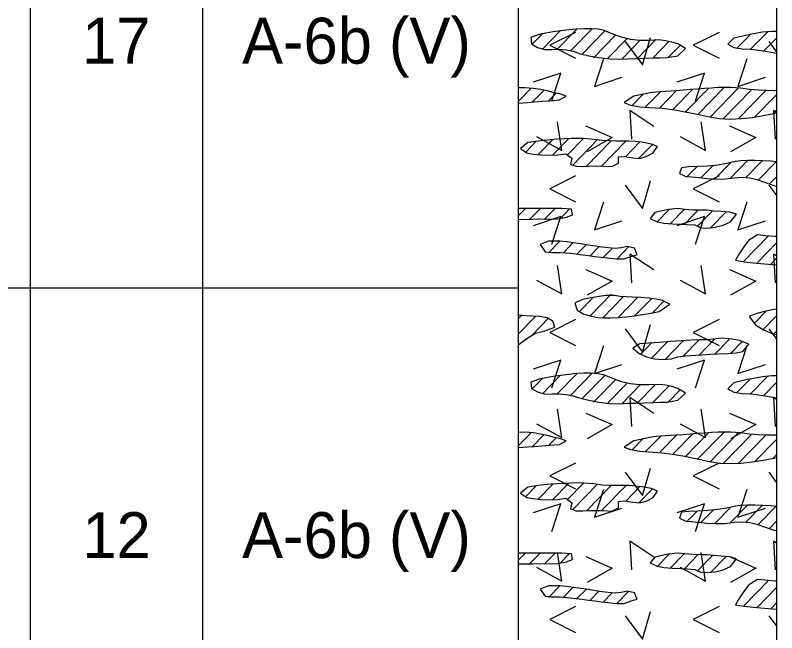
# Model space of a CAD drawing. Extents: x -0.01 to 0.83, y -0.63 to 1.27.
# Drawn here: x 0.7228 to 0.8333, y 0.237 to 0.3266 of the extents above; entities that cross this region are included whole.
import ezdxf

# ---------------------------------------------------------------- set-up
doc = ezdxf.new("R2010")
doc.units = 0

msp = doc.modelspace()

# ---------------------------------------------------------------- linework, layer by layer
for points in [[(0, 0), (0.83333, 0), (0.83333, 1.275), (0, 1.275)], [(0, 0), (0.83333, 0), (0.83333, 1.275), (0, 1.275)], [(0, 0), (0.83333, 0), (0.83333, 1.275), (0, 1.275)], [(0, 0), (0.83333, 0), (0.83333, 1.275), (0, 1.275)], [(0, 0), (0.83333, 0), (0.83333, 1.275), (0, 1.275)], [(0.79885, 0.32378), (0.79763, 0.32332), (0.79773, 0.32242), (0.79859, 0.3219), (0.7997, 0.3216), (0.80074, 0.32161), (0.80165, 0.32163), (0.80281, 0.32154), (0.80377, 0.32134), (0.80486, 0.32099), (0.80606, 0.32069), (0.80751, 0.32042), (0.80905, 0.32023), (0.81052, 0.3202), (0.81177, 0.32026), (0.81289, 0.3203), (0.81408, 0.32033), (0.81553, 0.32037), (0.81642, 0.3204), (0.81745, 0.32043), (0.81897, 0.3207), (0.82011, 0.32174), (0.81896, 0.32241), (0.8181, 0.32268), (0.81717, 0.32287), (0.81626, 0.32298), (0.81479, 0.32292), (0.81343, 0.32292), (0.8121, 0.32307), (0.8108, 0.32337), (0.80953, 0.32384), (0.8082, 0.32438), (0.80736, 0.32454), (0.8064, 0.32462), (0.80536, 0.32462), (0.80427, 0.32456), (0.80314, 0.32445), (0.80201, 0.32431), (0.8009, 0.32414), (0.79984, 0.32396)], [(0.83263, 0.32423), (0.83126, 0.32409), (0.82969, 0.32382), (0.82883, 0.32365), (0.82712, 0.32324), (0.82623, 0.32237), (0.82708, 0.32188), (0.82831, 0.32169), (0.82941, 0.32163), (0.83033, 0.32154), (0.83165, 0.32136), (0.83253, 0.32121), (0.83333, 0.32107), (0.83333, 0.32422)], [(0.79583, 0.31382), (0.79715, 0.31393), (0.79814, 0.31401), (0.79922, 0.31408), (0.80039, 0.31417), (0.80179, 0.31429), (0.80275, 0.31481), (0.80179, 0.31515), (0.80091, 0.31536), (0.80003, 0.31558), (0.79909, 0.31579), (0.79803, 0.31595), (0.79677, 0.31605), (0.79583, 0.31603)], [(0.82816, 0.31158), (0.82978, 0.31174), (0.83137, 0.312), (0.8329, 0.31231), (0.83333, 0.31241), (0.83333, 0.31565), (0.83295, 0.31562), (0.83188, 0.31564), (0.83071, 0.31569), (0.82938, 0.3158), (0.82807, 0.31597), (0.82662, 0.31609), (0.82576, 0.31609), (0.82484, 0.31606), (0.82387, 0.31601), (0.82286, 0.31594), (0.82182, 0.31586), (0.82077, 0.31578), (0.81973, 0.31569), (0.81872, 0.31562), (0.81715, 0.31552), (0.81579, 0.31543), (0.81491, 0.3153), (0.81357, 0.31502), (0.8126, 0.31481), (0.81121, 0.31389), (0.8121, 0.31353), (0.81345, 0.31329), (0.81479, 0.31319), (0.81668, 0.31309), (0.81818, 0.31289), (0.81905, 0.31275), (0.82, 0.31257), (0.82107, 0.31235), (0.82225, 0.3121), (0.82357, 0.31181), (0.82501, 0.31158), (0.82656, 0.31151)], [(0.79708, 0.30659), (0.79794, 0.30642), (0.79904, 0.3063), (0.80028, 0.30627), (0.80156, 0.30632), (0.80274, 0.30648), (0.80361, 0.30582), (0.80338, 0.30492), (0.80422, 0.30465), (0.80517, 0.30463), (0.80613, 0.30469), (0.8072, 0.30472), (0.80818, 0.30469), (0.80939, 0.30461), (0.81037, 0.30508), (0.81038, 0.30603), (0.8113, 0.30609), (0.81244, 0.3059), (0.81346, 0.30579), (0.81438, 0.30605), (0.81539, 0.30659), (0.81601, 0.30751), (0.81517, 0.30788), (0.81374, 0.30815), (0.81285, 0.30825), (0.81187, 0.30831), (0.81, 0.30831), (0.8091, 0.30833), (0.808, 0.3084), (0.80678, 0.30856), (0.8053, 0.30869), (0.80443, 0.3087), (0.80349, 0.30868), (0.80251, 0.30864), (0.80152, 0.30858), (0.80054, 0.3085), (0.79959, 0.30841), (0.7987, 0.30831), (0.79722, 0.30809), (0.79614, 0.30721)], [(0.83241, 0.30537), (0.83129, 0.30544), (0.83017, 0.30548), (0.8291, 0.30548), (0.82811, 0.30544), (0.82728, 0.30535), (0.82608, 0.30505), (0.82476, 0.30483), (0.8233, 0.30469), (0.82183, 0.30461), (0.82051, 0.30455), (0.81951, 0.30445), (0.81922, 0.30358), (0.82013, 0.30317), (0.82097, 0.30311), (0.822, 0.30301), (0.82318, 0.30288), (0.82448, 0.3028), (0.82584, 0.30282), (0.82719, 0.30299), (0.82836, 0.30305), (0.8294, 0.30297), (0.83043, 0.30274), (0.83156, 0.30235), (0.83291, 0.30186), (0.83333, 0.30178), (0.83333, 0.3053)], [(0.79583, 0.29696), (0.79676, 0.29695), (0.79792, 0.29697), (0.79882, 0.29701), (0.79992, 0.29697), (0.80151, 0.29701), (0.80282, 0.29727), (0.80367, 0.29759), (0.80354, 0.29843), (0.80216, 0.29851), (0.79583, 0.29851)], [(0.81822, 0.29632), (0.81944, 0.29626), (0.82033, 0.29622), (0.82145, 0.29615), (0.82229, 0.29574), (0.82324, 0.29569), (0.82438, 0.2958), (0.82555, 0.29609), (0.82662, 0.29659), (0.82749, 0.29769), (0.82651, 0.29799), (0.82524, 0.29809), (0.82413, 0.29815), (0.82324, 0.29826), (0.82226, 0.29828), (0.82121, 0.2983), (0.81995, 0.2984), (0.81902, 0.29851), (0.81761, 0.29837), (0.81566, 0.29793), (0.81496, 0.29709), (0.81598, 0.2966), (0.81695, 0.29642)], [(0.83305, 0.29446), (0.83171, 0.29457), (0.83054, 0.29468), (0.82925, 0.29386), (0.82857, 0.29294), (0.82792, 0.29205), (0.82735, 0.29103), (0.82858, 0.2908), (0.82945, 0.2907), (0.83045, 0.29061), (0.83155, 0.29051), (0.83272, 0.29041), (0.83333, 0.29036), (0.83333, 0.29445)], [(0.80066, 0.29216), (0.80188, 0.29215), (0.80339, 0.29202), (0.80423, 0.29193), (0.8051, 0.29182), (0.806, 0.2917), (0.80692, 0.29158), (0.80784, 0.29146), (0.80875, 0.29135), (0.81014, 0.29121), (0.81119, 0.29122), (0.81222, 0.29157), (0.81308, 0.29185), (0.81267, 0.29275), (0.8116, 0.293), (0.81075, 0.2928), (0.80989, 0.29272), (0.80885, 0.2928), (0.80799, 0.29291), (0.80703, 0.29306), (0.806, 0.29322), (0.80492, 0.29339), (0.80384, 0.29354), (0.8028, 0.29368), (0.80182, 0.29377), (0.8002, 0.29378), (0.79901, 0.2933), (0.79974, 0.29226)], [(0.81233, 0.28565), (0.81063, 0.28577), (0.80977, 0.28591), (0.8086, 0.28591), (0.80755, 0.28577), (0.80632, 0.28557), (0.80513, 0.28533), (0.80403, 0.28481), (0.80436, 0.28375), (0.80536, 0.28318), (0.80647, 0.28288), (0.8073, 0.28273), (0.80824, 0.28265), (0.80926, 0.28264), (0.81035, 0.2827), (0.81149, 0.2828), (0.81267, 0.28295), (0.81386, 0.28313), (0.81506, 0.28334), (0.81625, 0.28358), (0.81783, 0.28466), (0.81673, 0.28516), (0.81585, 0.28536), (0.8148, 0.28552), (0.81361, 0.28562)], [(0.79583, 0.27875), (0.79719, 0.27974), (0.79831, 0.28044), (0.79951, 0.28071), (0.80111, 0.28131), (0.80086, 0.28219), (0.80002, 0.28267), (0.79889, 0.28286), (0.79791, 0.28289), (0.79694, 0.28295), (0.79583, 0.28303)], [(0.83265, 0.28384), (0.83136, 0.28353), (0.83028, 0.28326), (0.82934, 0.28286), (0.83026, 0.28166), (0.83142, 0.2809), (0.83279, 0.28032), (0.83333, 0.28022), (0.83333, 0.28393)], [(0.82537, 0.27969), (0.82408, 0.27954), (0.82319, 0.27948), (0.82214, 0.27946), (0.82091, 0.27942), (0.81947, 0.27933), (0.81792, 0.27921), (0.81632, 0.27909), (0.81475, 0.279), (0.81348, 0.2789), (0.81247, 0.27826), (0.81337, 0.27749), (0.81444, 0.27699), (0.81561, 0.2767), (0.81675, 0.2766), (0.81807, 0.27671), (0.81896, 0.27698), (0.82003, 0.27713), (0.82157, 0.27725), (0.82253, 0.27731), (0.82362, 0.27737), (0.82483, 0.27743), (0.82618, 0.27749), (0.82745, 0.2776), (0.82842, 0.27778), (0.82927, 0.27883), (0.82791, 0.27935), (0.82679, 0.27955)], [(0.79885, 0.27378), (0.79763, 0.27332), (0.79773, 0.27242), (0.79859, 0.2719), (0.7997, 0.2716), (0.80074, 0.27161), (0.80165, 0.27163), (0.80281, 0.27154), (0.80377, 0.27134), (0.80486, 0.27099), (0.80606, 0.27069), (0.80751, 0.27042), (0.80905, 0.27023), (0.81052, 0.2702), (0.81177, 0.27026), (0.81289, 0.2703), (0.81408, 0.27033), (0.81553, 0.27037), (0.81642, 0.2704), (0.81745, 0.27043), (0.81897, 0.27071), (0.82011, 0.27174), (0.81896, 0.27241), (0.8181, 0.27268), (0.81717, 0.27287), (0.81626, 0.27298), (0.81479, 0.27292), (0.81343, 0.27292), (0.8121, 0.27307), (0.8108, 0.27338), (0.80953, 0.27384), (0.8082, 0.27438), (0.80736, 0.27454), (0.8064, 0.27462), (0.80536, 0.27462), (0.80427, 0.27456), (0.80314, 0.27445), (0.80201, 0.27431), (0.8009, 0.27414), (0.79984, 0.27396)], [(0.83263, 0.27423), (0.83126, 0.27409), (0.82969, 0.27382), (0.82883, 0.27365), (0.82712, 0.27324), (0.82623, 0.27237), (0.82708, 0.27188), (0.82831, 0.27169), (0.82941, 0.27163), (0.83033, 0.27154), (0.83165, 0.27136), (0.83253, 0.27121), (0.83333, 0.27107), (0.83333, 0.27422)], [(0.79583, 0.26382), (0.79715, 0.26393), (0.79814, 0.26401), (0.79922, 0.26408), (0.80039, 0.26417), (0.80179, 0.26429), (0.80275, 0.26481), (0.80179, 0.26515), (0.80091, 0.26536), (0.80003, 0.26558), (0.79909, 0.26579), (0.79803, 0.26595), (0.79677, 0.26605), (0.79583, 0.26603)], [(0.82816, 0.26158), (0.82978, 0.26174), (0.83137, 0.262), (0.8329, 0.26231), (0.83333, 0.26241), (0.83333, 0.26565), (0.83295, 0.26562), (0.83188, 0.26564), (0.83071, 0.26569), (0.82938, 0.2658), (0.82807, 0.26597), (0.82662, 0.26609), (0.82576, 0.26609), (0.82484, 0.26606), (0.82387, 0.26601), (0.82286, 0.26594), (0.82182, 0.26586), (0.82077, 0.26578), (0.81973, 0.26569), (0.81872, 0.26562), (0.81715, 0.26552), (0.81579, 0.26543), (0.81491, 0.2653), (0.81357, 0.26502), (0.8126, 0.26481), (0.81121, 0.26389), (0.8121, 0.26353), (0.81345, 0.26329), (0.81479, 0.26319), (0.81668, 0.26309), (0.81818, 0.26289), (0.81905, 0.26275), (0.82, 0.26257), (0.82107, 0.26235), (0.82225, 0.2621), (0.82357, 0.26181), (0.82501, 0.26158), (0.82656, 0.26151)], [(0.79708, 0.25659), (0.79794, 0.25642), (0.79904, 0.2563), (0.80028, 0.25627), (0.80156, 0.25632), (0.80274, 0.25648), (0.80361, 0.25582), (0.80338, 0.25492), (0.80422, 0.25465), (0.80517, 0.25463), (0.80613, 0.25469), (0.8072, 0.25472), (0.80818, 0.25469), (0.80939, 0.25461), (0.81037, 0.25508), (0.81038, 0.25603), (0.8113, 0.25609), (0.81244, 0.2559), (0.81346, 0.2558), (0.81438, 0.25605), (0.81539, 0.25659), (0.81601, 0.25751), (0.81517, 0.25788), (0.81374, 0.25815), (0.81285, 0.25825), (0.81187, 0.25831), (0.81, 0.25831), (0.8091, 0.25833), (0.808, 0.2584), (0.80678, 0.25856), (0.8053, 0.25869), (0.80443, 0.2587), (0.80349, 0.25868), (0.80251, 0.25864), (0.80152, 0.25858), (0.80054, 0.2585), (0.79959, 0.25841), (0.7987, 0.25831), (0.79722, 0.25809), (0.79614, 0.25721)], [(0.83241, 0.25537), (0.83129, 0.25544), (0.83017, 0.25548), (0.8291, 0.25548), (0.82811, 0.25544), (0.82728, 0.25535), (0.82608, 0.25505), (0.82476, 0.25483), (0.8233, 0.25469), (0.82183, 0.25461), (0.82051, 0.25455), (0.81951, 0.25445), (0.81922, 0.25358), (0.82013, 0.25317), (0.82097, 0.25311), (0.822, 0.25301), (0.82318, 0.25288), (0.82448, 0.2528), (0.82584, 0.25282), (0.82719, 0.25299), (0.82836, 0.25305), (0.8294, 0.25297), (0.83043, 0.25274), (0.83156, 0.25235), (0.83291, 0.25186), (0.83333, 0.25178), (0.83333, 0.2553)], [(0.79583, 0.24696), (0.79676, 0.24695), (0.79792, 0.24697), (0.79882, 0.24701), (0.79992, 0.24697), (0.80151, 0.24701), (0.80282, 0.24727), (0.80367, 0.24759), (0.80354, 0.24843), (0.80216, 0.24851), (0.79583, 0.24851)], [(0.81822, 0.24632), (0.81944, 0.24626), (0.82033, 0.24622), (0.82145, 0.24615), (0.82229, 0.24574), (0.82324, 0.24569), (0.82438, 0.2458), (0.82555, 0.24609), (0.82662, 0.24659), (0.82749, 0.24769), (0.82651, 0.24799), (0.82524, 0.24809), (0.82413, 0.24815), (0.82324, 0.24826), (0.82226, 0.24828), (0.82121, 0.2483), (0.81995, 0.2484), (0.81902, 0.24851), (0.81761, 0.24837), (0.81566, 0.24793), (0.81496, 0.24709), (0.81598, 0.2466), (0.81695, 0.24643)], [(0.83305, 0.24446), (0.83171, 0.24457), (0.83054, 0.24468), (0.82925, 0.24386), (0.82857, 0.24294), (0.82792, 0.24205), (0.82735, 0.24103), (0.82858, 0.2408), (0.82945, 0.2407), (0.83045, 0.24061), (0.83155, 0.24051), (0.83272, 0.24041), (0.83333, 0.24036), (0.83333, 0.24445)], [(0.80066, 0.24216), (0.80188, 0.24215), (0.80339, 0.24202), (0.80423, 0.24193), (0.8051, 0.24182), (0.806, 0.2417), (0.80692, 0.24158), (0.80784, 0.24146), (0.80875, 0.24135), (0.81014, 0.24121), (0.81119, 0.24122), (0.81222, 0.24157), (0.81308, 0.24185), (0.81267, 0.24275), (0.8116, 0.243), (0.81075, 0.2428), (0.80989, 0.24272), (0.80885, 0.2428), (0.80799, 0.24291), (0.80703, 0.24306), (0.806, 0.24322), (0.80492, 0.24339), (0.80384, 0.24354), (0.8028, 0.24368), (0.80182, 0.24377), (0.8002, 0.24378), (0.79901, 0.2433), (0.79974, 0.24226)]]:
    msp.add_lwpolyline(points, close=True)
for points in [[(0.725, 1.22083), (0.725, -0.62183)], [(0.75, 1.22083), (0.75, -0.62183)], [(0.75, 1.22083), (0.75, -0.62183)], [(0.79583, 1.22083), (0.79583, -0.62183)], [(0.725, 1.20833), (0.725, -0.62183)], [(0.83333, -0.62183), (0.83333, 1.13843)], [(0.79938, 0.32392), (0.79786, 0.32237)], [(0.79933, 0.32165), (0.80195, 0.32434)], [(0.80412, 0.32408), (0.80038, 0.32221), (0.80412, 0.32033)], [(0.80142, 0.32158), (0.8043, 0.32454)], [(0.80653, 0.32461), (0.8034, 0.3214)], [(0.80506, 0.32089), (0.8084, 0.32431)], [(0.82496, 0.32408), (0.82121, 0.32221), (0.82496, 0.32033)], [(0.83203, 0.32418), (0.82949, 0.32158)], [(0.80997, 0.32371), (0.80675, 0.3204)], [(0.81164, 0.3232), (0.80884, 0.32034)], [(0.81353, 0.32293), (0.81094, 0.32027)], [(0.81134, 0.32274), (0.81384, 0.31936), (0.81503, 0.32336)], [(0.81303, 0.32021), (0.81579, 0.32303)], [(0.81534, 0.32036), (0.81768, 0.32276)], [(0.82751, 0.32176), (0.82945, 0.32375)], [(0.83138, 0.3213), (0.83333, 0.3233)], [(0.83217, 0.32274), (0.83333, 0.32118)], [(0.8176, 0.32047), (0.81934, 0.32225)], [(0.83333, 0.32108), (0.83333, 0.32109)], [(0.80818, 0.32025), (0.80687, 0.31625), (0.81087, 0.31756)], [(0.82901, 0.32025), (0.8277, 0.31625), (0.8317, 0.31756)], [(0.80069, 0.31417), (0.802, 0.31817), (0.798, 0.31686)], [(0.82152, 0.31417), (0.82284, 0.31817), (0.81884, 0.31686)], [(0.82569, 0.31608), (0.82184, 0.31213)], [(0.79765, 0.31594), (0.79583, 0.31407)], [(0.7996, 0.31572), (0.79786, 0.31394)], [(0.8013, 0.31524), (0.80027, 0.31419)], [(0.81392, 0.31508), (0.81235, 0.31348)], [(0.8143, 0.31326), (0.8165, 0.31551)], [(0.8164, 0.31319), (0.81879, 0.31565)], [(0.81829, 0.31292), (0.82114, 0.31584)], [(0.82004, 0.3125), (0.82346, 0.316)], [(0.82775, 0.31598), (0.8237, 0.31183)], [(0.82964, 0.3157), (0.82557, 0.31152)], [(0.83173, 0.31563), (0.82774, 0.31154)], [(0.83333, 0.31506), (0.83012, 0.31176)], [(0.81551, 0.31044), (0.81201, 0.31276), (0.81226, 0.30857)], [(0.83281, 0.31231), (0.83333, 0.31284)], [(0.83333, 0.31243), (0.83284, 0.31276), (0.83309, 0.30857)], [(0.79847, 0.30896), (0.80215, 0.30696), (0.80153, 0.31109)], [(0.8193, 0.30896), (0.82299, 0.30696), (0.82236, 0.31109)], [(0.80562, 0.31051), (0.80946, 0.30882), (0.80581, 0.30676)], [(0.82645, 0.31051), (0.83029, 0.30882), (0.82664, 0.30676)], [(0.79871, 0.30634), (0.80085, 0.30853)], [(0.80083, 0.30629), (0.80311, 0.30863)], [(0.80534, 0.30871), (0.80299, 0.30629)], [(0.80367, 0.30478), (0.80732, 0.30852)], [(0.79844, 0.30828), (0.79691, 0.30671)], [(0.80571, 0.30466), (0.80924, 0.30828)], [(0.81142, 0.30829), (0.80785, 0.30464)], [(0.81141, 0.30607), (0.81348, 0.30819)], [(0.81528, 0.30783), (0.81331, 0.30581)], [(0.82433, 0.30281), (0.82666, 0.3052)], [(0.82909, 0.30548), (0.82656, 0.30289)], [(0.82885, 0.30301), (0.83122, 0.30544)], [(0.83325, 0.30531), (0.83065, 0.30265)], [(0.82035, 0.30315), (0.82176, 0.3046)], [(0.82233, 0.30298), (0.82408, 0.30476)], [(0.80412, 0.30325), (0.80038, 0.30137), (0.80412, 0.2995)], [(0.82496, 0.30325), (0.82121, 0.30137), (0.82496, 0.2995)], [(0.83333, 0.30318), (0.83227, 0.30209)], [(0.81134, 0.30191), (0.81384, 0.29853), (0.81503, 0.30253)], [(0.83217, 0.30191), (0.83333, 0.30035)], [(0.79583, 0.29748), (0.79681, 0.29848)], [(0.79898, 0.2985), (0.79747, 0.29695)], [(0.80116, 0.29852), (0.79959, 0.29691)], [(0.80328, 0.29848), (0.80188, 0.29704)], [(0.80818, 0.29942), (0.80687, 0.29542), (0.81087, 0.29673)], [(0.8177, 0.29837), (0.81596, 0.29659)], [(0.81988, 0.29839), (0.81785, 0.29632)], [(0.82901, 0.29942), (0.8277, 0.29542), (0.8317, 0.29673)], [(0.80069, 0.29334), (0.802, 0.29734), (0.798, 0.29602)], [(0.82152, 0.29334), (0.82284, 0.29734), (0.81884, 0.29602)], [(0.82185, 0.2982), (0.81997, 0.29628)], [(0.824, 0.29819), (0.82178, 0.29591)], [(0.82601, 0.29803), (0.82378, 0.29576)], [(0.83217, 0.29459), (0.82844, 0.29077)], [(0.80188, 0.29382), (0.8002, 0.29209)], [(0.8038, 0.29357), (0.80237, 0.29211)], [(0.80575, 0.29335), (0.80429, 0.29186)], [(0.80758, 0.29302), (0.80627, 0.29168)], [(0.81188, 0.293), (0.81016, 0.29124)], [(0.83333, 0.29357), (0.83052, 0.29069)], [(0.80941, 0.29269), (0.80816, 0.2914)], [(0.81551, 0.28961), (0.81201, 0.29192), (0.81226, 0.28773)], [(0.83333, 0.2916), (0.83284, 0.29192), (0.83309, 0.28773)], [(0.83333, 0.29136), (0.83245, 0.29045)], [(0.79847, 0.28813), (0.80215, 0.28613), (0.80153, 0.29025)], [(0.80562, 0.28967), (0.80946, 0.28799), (0.80581, 0.28593)], [(0.8193, 0.28813), (0.82299, 0.28613), (0.82236, 0.29025)], [(0.82645, 0.28967), (0.83029, 0.28799), (0.82664, 0.28593)], [(0.70417, 0.287), (0.725, 0.287)], [(0.725, 0.287), (0.75, 0.287)], [(0.75, 0.287), (0.79583, 0.287)], [(0.80465, 0.28354), (0.80667, 0.28561)], [(0.80626, 0.28297), (0.80928, 0.28607)], [(0.80809, 0.28264), (0.81111, 0.28574)], [(0.81041, 0.2828), (0.81318, 0.28564)], [(0.81264, 0.28288), (0.81518, 0.28548)], [(0.81536, 0.28345), (0.81699, 0.28512)], [(0.7963, 0.28299), (0.79583, 0.28251)], [(0.8301, 0.28188), (0.83184, 0.28366)], [(0.83131, 0.2809), (0.83333, 0.28298)], [(0.79834, 0.28286), (0.79583, 0.2803)], [(0.79786, 0.28016), (0.80023, 0.28259)], [(0.80412, 0.28241), (0.80038, 0.28054), (0.80412, 0.27866)], [(0.82496, 0.28241), (0.82121, 0.28054), (0.82496, 0.27866)], [(0.81134, 0.28107), (0.81384, 0.2777), (0.81503, 0.2817)], [(0.83217, 0.28107), (0.83333, 0.27951)], [(0.83285, 0.28027), (0.83333, 0.28076)], [(0.80818, 0.27858), (0.80687, 0.27458), (0.81087, 0.2759)], [(0.81519, 0.27906), (0.81354, 0.27736)], [(0.81514, 0.2768), (0.81748, 0.27919)], [(0.81709, 0.27658), (0.81974, 0.2793)], [(0.8197, 0.27704), (0.82203, 0.27943)], [(0.82202, 0.2772), (0.8243, 0.27954)], [(0.82431, 0.27733), (0.82644, 0.27953)], [(0.82663, 0.2775), (0.82834, 0.27925)], [(0.82901, 0.27858), (0.8277, 0.27458), (0.8317, 0.2759)], [(0.80069, 0.2725), (0.802, 0.2765), (0.798, 0.27519)], [(0.82152, 0.2725), (0.82284, 0.2765), (0.81884, 0.27519)], [(0.79933, 0.27165), (0.80195, 0.27434)], [(0.80142, 0.27158), (0.8043, 0.27454)], [(0.80653, 0.27461), (0.8034, 0.2714)], [(0.80506, 0.27089), (0.8084, 0.27431)], [(0.83203, 0.27418), (0.82949, 0.27158)], [(0.79938, 0.27392), (0.79786, 0.27237)], [(0.80997, 0.27371), (0.80675, 0.2704)], [(0.81164, 0.2732), (0.80884, 0.27034)], [(0.81303, 0.27021), (0.81579, 0.27303)], [(0.82751, 0.27176), (0.82945, 0.27375)], [(0.83138, 0.2713), (0.83333, 0.2733)], [(0.81353, 0.27293), (0.81094, 0.27027)], [(0.81534, 0.27036), (0.81768, 0.27276)], [(0.8176, 0.27047), (0.81934, 0.27225)], [(0.81551, 0.26878), (0.81201, 0.27109), (0.81226, 0.2669)], [(0.83333, 0.27077), (0.83284, 0.27109), (0.83309, 0.2669)], [(0.83333, 0.27108), (0.83333, 0.27109)], [(0.79847, 0.26729), (0.80215, 0.26529), (0.80153, 0.26942)], [(0.80562, 0.26884), (0.80946, 0.26716), (0.80581, 0.26509)], [(0.8193, 0.26729), (0.82299, 0.26529), (0.82236, 0.26942)], [(0.82645, 0.26884), (0.83029, 0.26716), (0.82664, 0.26509)], [(0.79765, 0.26594), (0.79583, 0.26407)], [(0.7996, 0.26572), (0.79786, 0.26394)], [(0.8013, 0.26524), (0.80027, 0.26419)], [(0.8143, 0.26326), (0.8165, 0.26551)], [(0.8164, 0.26319), (0.81879, 0.26565)], [(0.81829, 0.26292), (0.82114, 0.26584)], [(0.82004, 0.2625), (0.82346, 0.266)], [(0.82569, 0.26608), (0.82184, 0.26213)], [(0.82775, 0.26598), (0.8237, 0.26183)], [(0.82964, 0.2657), (0.82557, 0.26153)], [(0.83173, 0.26563), (0.82774, 0.26154)], [(0.81392, 0.26508), (0.81235, 0.26348)], [(0.83333, 0.26506), (0.83012, 0.26176)], [(0.83281, 0.26231), (0.83333, 0.26284)], [(0.80412, 0.26158), (0.80038, 0.25971), (0.80412, 0.25783)], [(0.81134, 0.26024), (0.81384, 0.25686), (0.81503, 0.26086)], [(0.82496, 0.26158), (0.82121, 0.25971), (0.82496, 0.25783)], [(0.83217, 0.26024), (0.83333, 0.25868)], [(0.80083, 0.25629), (0.80311, 0.25863)], [(0.80534, 0.25871), (0.80299, 0.25629)], [(0.79844, 0.25828), (0.79691, 0.25671)], [(0.79871, 0.25634), (0.80085, 0.25853)], [(0.80367, 0.25478), (0.80732, 0.25852)], [(0.80571, 0.25466), (0.80924, 0.25828)], [(0.80818, 0.25775), (0.80687, 0.25375), (0.81087, 0.25506)], [(0.81142, 0.25829), (0.80785, 0.25464)], [(0.81141, 0.25607), (0.81348, 0.25819)], [(0.81528, 0.25783), (0.81331, 0.25581)], [(0.82901, 0.25775), (0.8277, 0.25375), (0.8317, 0.25506)], [(0.80069, 0.25167), (0.802, 0.25567), (0.798, 0.25436)], [(0.82152, 0.25167), (0.82284, 0.25567), (0.81884, 0.25436)], [(0.82909, 0.25548), (0.82656, 0.25289)], [(0.82885, 0.25301), (0.83122, 0.25544)], [(0.83325, 0.25531), (0.83065, 0.25265)], [(0.82035, 0.25315), (0.82176, 0.2546)], [(0.82233, 0.25298), (0.82408, 0.25476)], [(0.82433, 0.25281), (0.82666, 0.2552)], [(0.83333, 0.25318), (0.83227, 0.25209)], [(0.81551, 0.24794), (0.81201, 0.25026), (0.81226, 0.24607)], [(0.83333, 0.24993), (0.83284, 0.25026), (0.83309, 0.24607)], [(0.79583, 0.24748), (0.79681, 0.24848)], [(0.79898, 0.2485), (0.79747, 0.24695)], [(0.79847, 0.24646), (0.80215, 0.24446), (0.80153, 0.24859)], [(0.80116, 0.24852), (0.79959, 0.24691)], [(0.80328, 0.24848), (0.80188, 0.24704)], [(0.80562, 0.24801), (0.80946, 0.24632), (0.80581, 0.24426)], [(0.8177, 0.24837), (0.81596, 0.24659)], [(0.81988, 0.24839), (0.81785, 0.24632)], [(0.8193, 0.24646), (0.82299, 0.24446), (0.82236, 0.24859)], [(0.82185, 0.2482), (0.81997, 0.24628)], [(0.824, 0.24819), (0.82178, 0.24591)], [(0.82601, 0.24803), (0.82378, 0.24576)], [(0.82645, 0.24801), (0.83029, 0.24632), (0.82664, 0.24426)], [(0.83217, 0.24459), (0.82844, 0.24077)], [(0.80188, 0.24382), (0.8002, 0.24209)], [(0.8038, 0.24357), (0.80237, 0.24211)], [(0.80575, 0.24335), (0.80429, 0.24186)], [(0.83333, 0.24357), (0.83052, 0.24069)], [(0.80758, 0.24302), (0.80627, 0.24168)], [(0.80941, 0.24269), (0.80816, 0.2414)], [(0.81188, 0.243), (0.81016, 0.24124)], [(0.83333, 0.24136), (0.83245, 0.24045)], [(0.80412, 0.24075), (0.80038, 0.23887), (0.80412, 0.237)], [(0.81134, 0.23941), (0.81384, 0.23603), (0.81503, 0.24003)], [(0.82496, 0.24075), (0.82121, 0.23887), (0.82496, 0.237)], [(0.83217, 0.23941), (0.83333, 0.23785)]]:
    msp.add_lwpolyline(points)

# ---------------------------------------------------------------- texts
for s, p in [('17', (0.73253, 0.31954)), ('A-6b (V)', (0.75575, 0.31954)), ('12', (0.73257, 0.24779)), ('A-6b (V)', (0.75575, 0.24779))]:
    msp.add_text(s, height=0.006667).set_placement(p)

doc.saveas('drawing.dxf')
